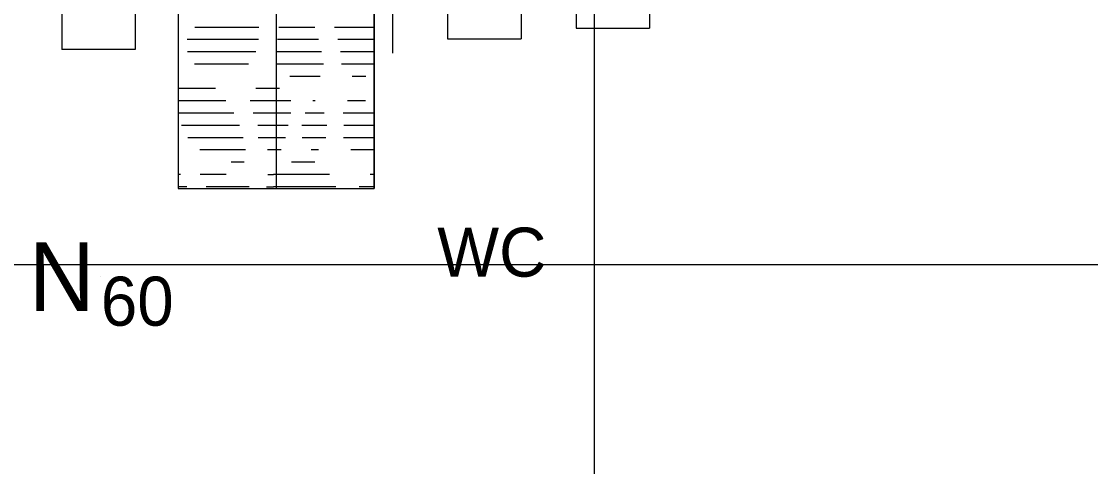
# Model space of a CAD drawing. Extents: x -2280229 to 1306, y -58886 to 440.
# Drawn here: x 461.59 to 505.23, y 53.96 to 72.12 of the extents above; entities that cross this region are included whole.
import ezdxf

# ---------------------------------------------------------------- set-up
doc = ezdxf.new("R2010")
doc.units = 0
for name, color, linetype in [('BR_P_Sub_Deep_Object', 7, 'Continuous'), ('GT_Project_Soil_Layers', 7, 'Continuous'), ('SC_Scratch2', 7, 'Continuous'), ('SC_Scratch3', 7, 'Continuous'), ('SC_Scratch9', 7, 'Continuous'), ('SH_Minor_Grid_Line', 7, 'Continuous')]:
    doc.layers.add(name, color=color, linetype=linetype)

msp = doc.modelspace()

# ---------------------------------------------------------------- linework, layer by layer
at = {"layer": 'BR_P_Sub_Deep_Object'}
for p, q in [((463.234, 106.302), (463.234, 70.968)), ((466.234, 106.287), (466.234, 70.968)), ((476.734, 106.22), (476.734, 70.824)), ((478.984, 106.201), (478.984, 71.405)), ((481.984, 106.186), (481.984, 71.405)), ((484.234, 106.167), (484.234, 71.844)), ((487.234, 106.153), (487.234, 71.844)), ((484.234, 71.844), (487.234, 71.844)), ((478.984, 71.405), (481.984, 71.405)), ((466.234, 70.968), (463.234, 70.968))]:
    msp.add_line(p, q, dxfattribs=at)
at = {"layer": 'GT_Project_Soil_Layers'}
for p, q in [((471.28, 71.875), (468.663, 71.875)), ((473.562, 71.875), (472.097, 71.875)), ((475.984, 71.875), (474.366, 71.875)), ((471.263, 71.375), (468.352, 71.375)), ((473.717, 71.375), (472.048, 71.375)), ((475.984, 71.375), (474.501, 71.375)), ((471.159, 70.875), (468.369, 70.875)), ((473.845, 70.875), (471.986, 70.875)), ((475.984, 70.875), (474.615, 70.875)), ((470.864, 70.375), (468.657, 70.375)), ((473.92, 70.375), (471.993, 70.375)), ((475.984, 70.375), (474.658, 70.375)), ((473.781, 69.875), (472.551, 69.875)), ((475.655, 69.875), (475.096, 69.875)), ((469.514, 69.375), (468.027, 69.375)), ((471.882, 69.375), (471.159, 69.375)), ((472.121, 69.375), (471.882, 69.375)), ((469.934, 68.875), (467.984, 68.875)), ((471.882, 68.875), (470.927, 68.875)), ((472.584, 68.875), (471.882, 68.875)), ((473.581, 68.875), (473.488, 68.875)), ((475.638, 68.875), (474.902, 68.875)), ((470.26, 68.375), (467.984, 68.375)), ((471.882, 68.375), (471.052, 68.375)), ((472.592, 68.375), (471.882, 68.375)), ((473.955, 68.375), (473.167, 68.375)), ((475.96, 68.375), (474.724, 68.375)), ((470.491, 67.875), (468.121, 67.875)), ((471.882, 67.875), (471.245, 67.875)), ((472.484, 67.875), (471.882, 67.875)), ((474.057, 67.875), (473.041, 67.875)), ((475.984, 67.875), (474.752, 67.875)), ((470.646, 67.375), (468.386, 67.375)), ((471.882, 67.375), (471.248, 67.375)), ((472.374, 67.375), (471.882, 67.375)), ((474.019, 67.375), (473.053, 67.375)), ((475.984, 67.375), (474.735, 67.375)), ((470.732, 66.875), (468.873, 66.875)), ((471.882, 66.875), (471.635, 66.875)), ((472.195, 66.875), (471.882, 66.875)), ((473.72, 66.875), (473.42, 66.875)), ((475.984, 66.875), (475.034, 66.875)), ((470.683, 66.375), (470.158, 66.375)), ((473.57, 66.375), (472.609, 66.375)), ((468.085, 65.875), (467.984, 65.875)), ((469.953, 65.875), (468.885, 65.875)), ((471.655, 65.875), (471.882, 65.875)), ((474.16, 65.875), (471.882, 65.875)), ((475.984, 65.875), (475.824, 65.875)), ((468.341, 65.375), (467.984, 65.375)), ((470.893, 65.375), (469.127, 65.375)), ((471.591, 65.375), (471.882, 65.375)), ((474.42, 65.375), (471.882, 65.375)), ((475.984, 65.375), (475.376, 65.375))]:
    msp.add_line(p, q, dxfattribs=at)
msp.add_lwpolyline([(467.984, 65.308), (475.984, 65.308), (475.984, 80.308), (467.984, 80.308)], close=True, dxfattribs=at)
at = {"layer": 'SC_Scratch2'}
for p, q in [((467.984, 107.308), (467.984, 65.308)), ((471.984, 107.308), (471.984, 65.308)), ((475.984, 107.308), (475.984, 65.308)), ((467.984, 65.308), (475.984, 65.308))]:
    msp.add_line(p, q, dxfattribs=at)
at = {"layer": 'SC_Scratch3'}
msp.add_line((464.832, 61.708), (464.832, 61.708), dxfattribs=at)
at = {"layer": 'SH_Minor_Grid_Line'}
for p, q in [((484.984, 21.221), (484.984, 162.208)), ((45.429, 62.208), (603.007, 62.208))]:
    msp.add_line(p, q, dxfattribs=at)

# ---------------------------------------------------------------- texts
at = {"layer": 'SC_Scratch3'}
for s, height, p in [('N', 2.8, (461.888, 60.308)), ('60', 2, (464.832, 59.708))]:
    msp.add_text(s, height=height, dxfattribs=at).set_placement(p)
at = {"layer": 'SC_Scratch9'}
msp.add_text('WC', height=2, dxfattribs=at).set_placement((478.564, 61.708))

doc.saveas('drawing.dxf')
